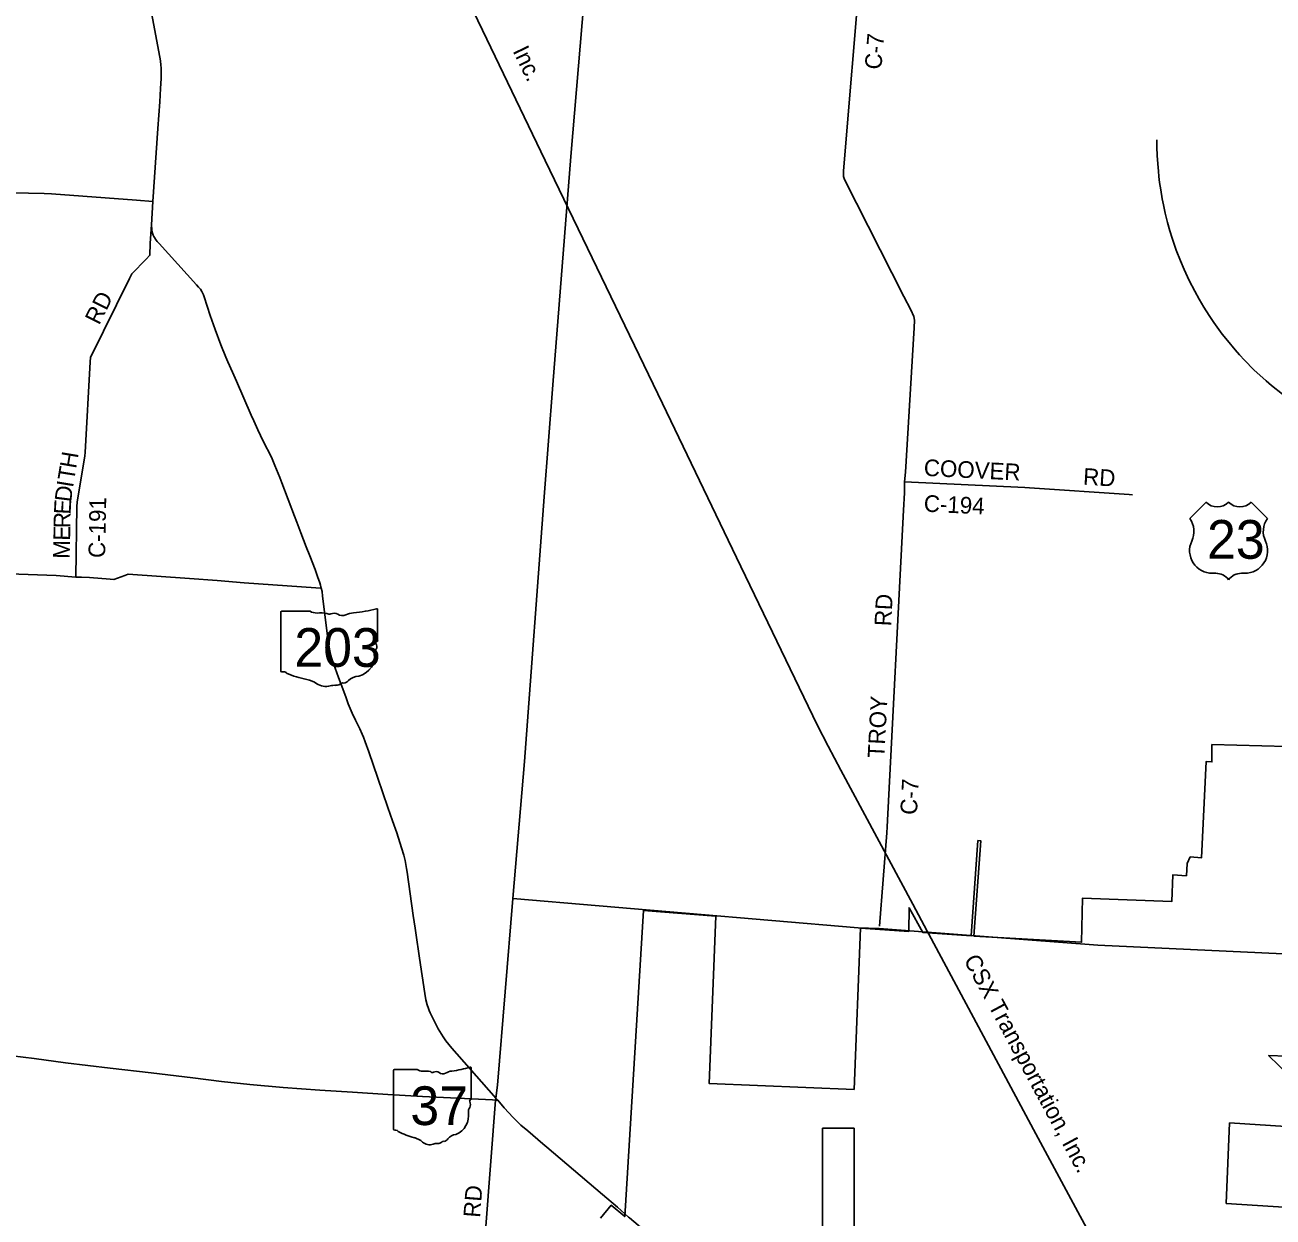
# Model space of a CAD drawing. Extents: x 1674899 to 2057726, y 653888 to 988278.
# Drawn here: x 1785762 to 1808187, y 843541 to 864966 of the extents above; entities that cross this region are included whole.
import ezdxf

# ---------------------------------------------------------------- set-up
doc = ezdxf.new("R2010")
doc.units = 0
for name, color, linetype in [('GM_X_Corporation', 7, 'Continuous'), ('GM_X_County_Road', 7, 'Continuous'), ('GM_X_County_Road_Text', 7, 'Continuous'), ('GM_X_Rail_Line', 7, 'Continuous'), ('GM_X_Rail_Line_Text', 7, 'Continuous'), ('GM_X_State_Location', 7, 'Continuous'), ('GM_X_State_Route', 7, 'Continuous'), ('GM_X_State_Shield', 7, 'Continuous'), ('GM_X_Township', 7, 'Continuous'), ('GM_X_US_Shield', 7, 'Continuous')]:
    doc.layers.add(name, color=color, linetype=linetype)

msp = doc.modelspace()

# ---------------------------------------------------------------- linework, layer by layer
at = {"layer": 'GM_X_Corporation'}
for points in [[(1796105, 843523), (1796297, 843753), (1796540, 843550), (1796878, 849051), (1798177, 848946), (1798053, 845944), (1800661, 845836), (1800775, 848735), (1801643, 848675), (1801648, 849101), (1801894, 848657), (1802762, 848594), (1802886, 850307), (1802936, 850304), (1802812, 848592), (1804746, 848481), (1804763, 849272), (1806371, 849213), (1806387, 849693), (1806631, 849675), (1806647, 849895), (1806700, 850012), (1806903, 849998), (1806985, 851728), (1807088, 851722), (1807090, 852031), (1808433, 851997)], [(1808433, 846432), (1808107, 846444), (1808850, 845724)], [(1808419, 845169), (1807406, 845234), (1807346, 843787), (1810722, 843570)]]:
    msp.add_lwpolyline(points, dxfattribs=at)
msp.add_lwpolyline([(1800095, 845138), (1800097, 841137), (1800439, 841067), (1800851, 841077), (1800851, 841367), (1800661, 841367), (1800659, 845138)], close=True, dxfattribs=at)
at = {"layer": 'GM_X_County_Road'}
for points in [[(1801567, 856755), (1801567, 856755), (1801584, 856930), (1801742, 859524), (1801746, 859662), (1801732, 859727), (1801677, 859846), (1801556, 860087), (1800489, 862190), (1800471, 862240), (1800469, 862342), (1800776, 866006), (1800811, 866452), (1800848, 866888), (1800911, 867730), (1800965, 868323), (1801008, 868838), (1801046, 869299), (1801092, 869835), (1801238, 871613)], [(1777970, 862741), (1780778, 862248), (1780868, 862232), (1784609, 861971), (1784696, 861964), (1786106, 861939), (1786241, 861929)], [(1786241, 861929), (1787766, 861819), (1788057, 861796)], [(1786675, 855044), (1786697, 856311), (1786698, 856387), (1786835, 857221), (1786845, 857279), (1786936, 858914), (1786940, 858987), (1787642, 860408), (1787683, 860493), (1787941, 860759), (1788006, 860826), (1788012, 861039), (1788018, 861131), (1788033, 861371)], [(1801549, 856244), (1801549, 856244), (1801565, 856560), (1801567, 856755)], [(1801567, 856755), (1803730, 856654), (1803812, 856649), (1805603, 856528), (1805663, 856523)], [(1801256, 850553), (1801549, 856244)], [(1785318, 855106), (1786321, 855070), (1786675, 855044), (1786776, 855041), (1786778, 855041)], [(1786778, 855041), (1786924, 855037), (1787292, 855007), (1787356, 855002), (1787555, 855074), (1787618, 855096), (1788721, 855019), (1789216, 854979), (1789701, 854941), (1790989, 854849), (1791087, 854843)], [(1801117, 848771), (1801250, 850449), (1801256, 850553)], [(1793847, 840780), (1793954, 842199), (1794218, 845643)]]:
    msp.add_lwpolyline(points, dxfattribs=at)
at = {"layer": 'GM_X_Rail_Line'}
for points in [[(1801975, 848676), (1801713, 849164), (1800422, 851570), (1800191, 852004), (1799998, 852388), (1798549, 855396), (1797216, 858165), (1795112, 862528), (1793984, 864870), (1792306, 868354)], [(1808358, 858329), (1808159, 858489), (1808066, 858568), (1807844, 858768), (1807674, 858942), (1807585, 859038), (1807506, 859128), (1807367, 859293), (1807274, 859411), (1807214, 859493), (1807122, 859620), (1807041, 859742), (1806945, 859894), (1806858, 860039), (1806780, 860181), (1806680, 860373), (1806591, 860569), (1806522, 860729), (1806449, 860920), (1806376, 861133), (1806334, 861268), (1806294, 861413), (1806251, 861584), (1806218, 861732), (1806197, 861844), (1806171, 862002), (1806150, 862136), (1806137, 862241), (1806127, 862337), (1806116, 862471), (1806107, 862620), (1806101, 862772), (1806101, 862904)], [(1802002, 848627), (1801975, 848676)], [(1805801, 841464), (1805790, 841494), (1805760, 841576), (1805705, 841712), (1805651, 841827), (1805601, 841928), (1805556, 842011), (1803926, 845037), (1802002, 848627)]]:
    msp.add_lwpolyline(points, dxfattribs=at)
at = {"layer": 'GM_X_State_Route'}
for points in [[(1794187, 845719), (1793434, 846579), (1793324, 846710), (1793274, 846777), (1793187, 846924), (1793100, 847093), (1793045, 847210), (1793027, 847252), (1793013, 847289), (1792991, 847355), (1792967, 847443), (1792946, 847558), (1792850, 848193), (1792784, 848652), (1792773, 848731), (1792740, 848959), (1792628, 849742), (1792619, 849803), (1792592, 849950), (1792568, 850047), (1792530, 850174), (1792441, 850445), (1792367, 850662), (1792285, 850899), (1792105, 851429), (1791940, 851905), (1791877, 852084), (1791846, 852163), (1791822, 852220), (1791780, 852313), (1791755, 852366), (1791702, 852474), (1791642, 852598), (1791571, 852765), (1791525, 852890), (1791444, 853113), (1791397, 853241), (1791277, 853572), (1791258, 853631), (1791244, 853685), (1791226, 853784), (1791205, 853939), (1791111, 854702), (1791100, 854784), (1791087, 854843), (1791073, 854900), (1791061, 854942), (1791021, 855052), (1790974, 855179), (1790879, 855426), (1790817, 855588), (1790721, 855839), (1790647, 856032), (1790607, 856138), (1790378, 856737), (1790341, 856833), (1790254, 857050), (1790190, 857197), (1790044, 857488), (1789945, 857688), (1789872, 857851), (1789828, 857951), (1789562, 858562), (1789490, 858725), (1789407, 858912), (1789372, 858995), (1789284, 859215), (1789180, 859492), (1789091, 859742), (1788985, 860077), (1788969, 860118), (1788940, 860175), (1788914, 860215), (1788880, 860256), (1788847, 860293), (1788174, 861037), (1788137, 861075), (1788121, 861096), (1788106, 861118), (1788089, 861147), (1788079, 861165), (1788068, 861189), (1788050, 861239), (1788039, 861291), (1788033, 861371), (1788057, 861796), (1788151, 863108), (1788185, 863584), (1788200, 863823), (1788208, 864005), (1788211, 864101), (1788210, 864149), (1788208, 864198), (1788204, 864245), (1788195, 864319), (1787933, 865736)], [(1782747, 846479), (1782794, 846480), (1783183, 846484), (1783377, 846485), (1783923, 846492), (1784269, 846503), (1784713, 846520), (1784920, 846517), (1785189, 846487), (1785532, 846441), (1785928, 846388), (1786488, 846310), (1787292, 846217), (1788027, 846133), (1788780, 846042), (1789296, 845980), (1789805, 845926), (1790403, 845872), (1791058, 845819), (1791646, 845786), (1792283, 845741), (1792907, 845707), (1794165, 845645)], [(1794256, 845640), (1794225, 845677), (1794187, 845719)], [(1794165, 845645), (1794218, 845643), (1794256, 845640)], [(1794256, 845640), (1794372, 845506), (1794532, 845328), (1794610, 845252), (1794673, 845195), (1794795, 845090), (1795070, 844854), (1795139, 844795), (1795501, 844493), (1796141, 843947), (1796409, 843716), (1796609, 843541)], [(1796609, 843541), (1796627, 843525), (1796897, 843295), (1796897, 843295)]]:
    msp.add_lwpolyline(points, dxfattribs=at)
at = {"layer": 'GM_X_State_Shield'}
for p, q in [((1790359, 854412), (1790359, 853356)), ((1790886, 854431), (1790376, 854431)), ((1792099, 853904), (1792099, 854457)), ((1792099, 853904), (1792099, 853904)), ((1792386, 846176), (1792386, 845119)), ((1792808, 846194), (1792400, 846194)), ((1793778, 845667), (1793778, 846220)), ((1793778, 845667), (1793778, 845667))]:
    msp.add_line(p, q, dxfattribs=at)
for centre, radius, start, end in [((1792402, 846178), 16.1, 98.1301, 188.1301), ((1792905, 846317), 156, 231.6195, 271.1119), ((1792957, 845601), 562, 80.4867, 94.9883), ((1793084, 846183), 45.1, 219.7921, 297.1024), ((1793150, 846061), 93.8, 54.4667, 119.1411), ((1793271, 846229), 113, 233.8562, 294.8282), ((1793471, 845871), 297, 97.3462, 120.7689), ((1793282, 847634), 1476, 275.8445, 288.9065), ((1793763, 846222), 15.5, 351.8621, 97.738), ((1793762, 845665), 16.6, 289.6038, 7.7341), ((1793834, 845436), 105, 136.8065, 186.9296), ((1793775, 845627), 24, 107.944, 210.337), ((1793622, 845557), 144, 340.033, 23.6496), ((1793365, 845366), 369, 292.3089, 8.9858), ((1792402, 845117), 16.3, 171.9584, 258.3066), ((1792405, 845225), 124, 267.339, 280.6039), ((1792430, 845058), 44.8, 29.7484, 93.2717), ((1792995, 846007), 1066, 240.4129, 257.1985), ((1793521, 844822), 202, 94.4031, 142.5768), ((1792678, 844644), 334, 47.1842, 75.836), ((1793038, 845053), 212, 230.7004, 286.2918), ((1793161, 844688), 174, 85.6951, 111.2099), ((1793176, 844974), 113, 268.777, 315.5493), ((1793278, 844871), 31.8, 65.7517, 132.6484), ((1793265, 845017), 119, 282.8732, 323.2771)]:
    msp.add_arc(centre, radius, start, end, dxfattribs=at)
for centre, major_axis, start_param, end_param in [((1790379, 854415), (20.2, 0), 1.712693, 3.28349), ((1791007, 854553), (196, 0), 4.042523, 4.731795), ((1791715, 854108), (371, 0), 1.699011, 2.107814), ((1791480, 855871), (1845, 0), 4.814394, 5.042369), ((1792080, 854459), (19.4, 0), 6.141152, 7.989035), ((1791072, 853837), (702, 0), 1.404758, 1.657858), ((1791232, 854420), (56.4, 0), 3.836095, 5.185415), ((1791314, 854298), (117, 0), 0.950623, 2.079405), ((1791466, 854466), (141, 0), 4.081561, 5.145723), ((1792169, 853673), (131, 0), 2.387724, 3.262537), ((1792095, 853864), (30, 0), 1.883978, 3.671073), ((1791904, 853794), (180, 0), 5.934695, 6.695948), ((1792079, 853902), (20.7, 0), 5.05454, 6.418171), ((1791583, 853602), (462, 0), 5.101752, 6.440018), ((1790379, 853354), (20.3, 0), 3.00124, 4.508301), ((1790382, 853462), (155, 0), 4.665946, 4.897461), ((1790414, 853295), (56, 0), 0.519207, 1.627899), ((1791121, 854244), (1333, 0), 4.195997, 4.488961), ((1790724, 852881), (417, 0), 0.823519, 1.323587), ((1791174, 853290), (265, 0), 4.026481, 4.996735), ((1791327, 852924), (217, 0), 1.495662, 1.94098), ((1791347, 853211), (141, 0), 4.691044, 5.507374), ((1791474, 853108), (39.7, 0), 1.147584, 2.315152), ((1791457, 853253), (149, 0), 4.937069, 5.64225), ((1791778, 853059), (253, 0), 1.647645, 2.488434)]:
    msp.add_ellipse(centre, major_axis=major_axis, ratio=0.8, start_param=start_param, end_param=end_param, dxfattribs=at)
at = {"layer": 'GM_X_Township'}
msp.add_lwpolyline([(1794528, 849265), (1794738, 851729), (1795090, 856488), (1795247, 858499), (1795573, 862604), (1796250, 870609), (1796651, 875449), (1801483, 875120), (1808584, 874680), (1818820, 874127), (1822583, 873901), (1822382, 871013), (1821956, 864281), (1821820, 862138), (1821743, 860915), (1821306, 853784), (1821204, 851968), (1820950, 847472), (1816586, 847751), (1810328, 848152), (1809012, 848241), (1805038, 848430), (1801113, 848728), (1800736, 848740)], close=True, dxfattribs=at)
for points in [[(1796250, 870609), (1795573, 862604), (1795247, 858499), (1795090, 856488), (1794738, 851729), (1794528, 849265), (1794250, 845913), (1794225, 845677), (1794218, 845643), (1793954, 842199)], [(1793954, 842199), (1794218, 845643), (1794225, 845677), (1794250, 845913), (1794528, 849265), (1800736, 848740), (1801113, 848728), (1805038, 848430), (1809012, 848241)]]:
    msp.add_lwpolyline(points, dxfattribs=at)
at = {"layer": 'GM_X_US_Shield'}
for p, q in [((1806983, 856387), (1806693, 856097)), ((1808085, 856097), (1807795, 856387)), ((1807099, 855111), (1807157, 855111)), ((1807621, 855111), (1807679, 855111))]:
    msp.add_line(p, q, dxfattribs=at)
for centre, radius, start, end in [((1807186, 856594), 290, 225.573, 314.427), ((1807592, 856594), 290, 225.573, 314.427), ((1806360, 855864), 406, 334.5471, 35.0009), ((1808418, 855864), 406, 144.9991, 205.4529), ((1807094, 855517), 406, 154.8319, 270.6383), ((1807683, 855517), 406, 269.3617, 25.1681), ((1807157, 854821), 290, 36.8699, 90), ((1807621, 854821), 290, 90, 143.1301)]:
    msp.add_arc(centre, radius, start, end, dxfattribs=at)

# ---------------------------------------------------------------- texts
at = {"layer": 'GM_X_County_Road_Text'}
for s, rotation, p in [('C-7', 85.4268, (1801149, 864157)), ('RD', 63.4349, (1787094, 859559)), ('H', 80.4832, (1786681, 856983)), ('COOVER', 357.1629, (1801907, 856863)), ('T', 80.6849, (1786644, 856762)), ('RD', 356.5467, (1804768, 856704)), ('D', 82.8985, (1786592, 856382)), ('I', 80.7532, (1786625, 856641)), ('E', 86.9364, (1786581, 856163)), ('C-191', 88.8984, (1787202, 855384)), ('C-194', 357.2469, (1801907, 856220)), ('R', 88.9618, (1786576, 855919)), ('E', 89.0099, (1786573, 855695)), ('M', 89.012, (1786567, 855370)), ('RD', 87.0388, (1801325, 854155)), ('TROY', 86.9742, (1801202, 851783)), ('C-7', 86.7948, (1801788, 850763)), ('RD', 85.5632, (1793938, 843523))]:
    msp.add_text(s, height=300, rotation=rotation, dxfattribs=at).set_placement(p)
at = {"layer": 'GM_X_Rail_Line_Text'}
for s, rotation, p in [('Inc.', 295.8111, (1794520, 864501)), ('CSX Transportation, Inc.', 298.2075, (1802622, 848163))]:
    msp.add_text(s, height=299, rotation=rotation, dxfattribs=at).set_placement(p)
at = {"layer": 'GM_X_State_Location'}
for s, p in [('203', (1790857, 853741)), ('37', (1792815, 845504))]:
    msp.add_text(s, height=1, rotation=0, dxfattribs=at).set_placement(p)
for s, p in [('s', (1791210, 853814)), ('r', (1791210, 853814)), ('s', (1793067, 845577)), ('r', (1793067, 845577))]:
    msp.add_text(s, height=1, dxfattribs=at).set_placement(p)
at = {"layer": 'GM_X_State_Shield'}
for s, p in [('203', (1790602, 853430)), ('37', (1792687, 845194))]:
    msp.add_text(s, height=696.1, dxfattribs=at).set_placement(p)
at = {"layer": 'GM_X_US_Shield'}
msp.add_text('23', height=696.1, dxfattribs=at).set_placement((1807001, 855372))

doc.saveas('drawing.dxf')
